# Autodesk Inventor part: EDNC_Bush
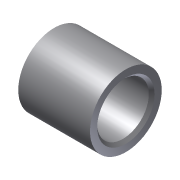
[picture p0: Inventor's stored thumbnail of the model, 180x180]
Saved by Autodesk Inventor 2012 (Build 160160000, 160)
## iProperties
Created: 2010-10
Part Number: EDNC_Bush
Document SubType Name: Modeling
Designer: JSSONG
Density: 1 g/cm^3
Mass: 5.85148 g
Surface Area: 37.8637 cm^2
Volume: 5.85148 cm^3
Material: 기본값
Author: JSSONG
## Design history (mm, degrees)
sketch "스케치1"
  geometry: L1 (0, 0)-(0, 12.5); L2 (0, 12.5)-(25, 12.5); L3 (25, 12.5)-(25, 0); L4 (25, 0)-(0, 0); L5 (0, 9)-(25, 9)
  constraints: 10 end point, 2 parallel, 2 perpendicular, 2 point on line, 1 vertical
  dimensions: "d0" = 25 diameter of L2 L4; "d1" = 18 diameter of L5 L4; "d2" = 25 distance of L1.end L2.end
revolve "회전1" sketch "스케치1" stored, may be unused: angle "d3" = 90 deg
chamfer "모따기1" distance "d4" = 1; stored, may be unused: second distance "d5" = 2, angle "d6" = 45 deg
node "솔리드1"
